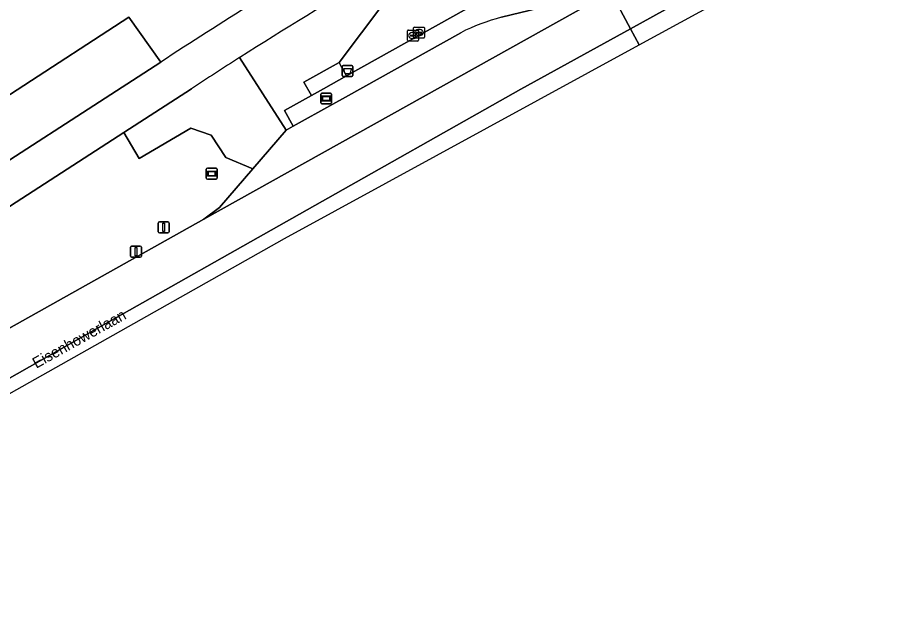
# Model space of a CAD drawing. Extents: x 162417 to 163722, y 384268 to 385417.
# Drawn here: x 163642.7 to 163721.7, y 384656 to 384709.9 of the extents above; entities that cross this region are included whole.
import ezdxf

# ---------------------------------------------------------------- set-up
doc = ezdxf.new("R2010")
doc.units = 0
for name, color, linetype in [('IMGEO_Afvalbak', 7, 'Continuous'), ('IMGEO_Berm_groen', 7, 'Continuous'), ('IMGEO_Fietspad_gesloten', 7, 'Continuous'), ('IMGEO_Informatiebord', 7, 'Continuous'), ('IMGEO_Lichtmast', 7, 'Continuous'), ('IMGEO_Openbare_ruimte_label', 7, 'Continuous'), ('IMGEO_Reclamebord', 7, 'Continuous'), ('IMGEO_Rijbaan_lokaal_open', 7, 'Continuous'), ('IMGEO_Rijbaan_regionaal_gesloten', 7, 'Continuous'), ('IMGEO_Rioolput', 7, 'Continuous'), ('IMGEO_Terreindeel_gesloten', 7, 'Continuous'), ('IMGEO_Terreindeel_halfverhard', 7, 'Continuous'), ('IMGEO_Verkeersbordpaal', 7, 'Continuous'), ('IMGEO_Voetpad_halfverhard', 7, 'Continuous'), ('IMGEO_Voetpad_open', 7, 'Continuous')]:
    doc.layers.add(name, color=color, linetype=linetype)

msp = doc.modelspace()

# ---------------------------------------------------------------- linework, layer by layer
at = {"layer": 'IMGEO_Afvalbak'}
for p, q in [((163672.383, 384704.576), (163672.383, 384705.376)), ((163672.383, 384705.376), (163672.383, 384704.576)), ((163672.483, 384705.476), (163673.273, 384705.476)), ((163673.273, 384705.476), (163672.483, 384705.476)), ((163673.373, 384705.376), (163673.373, 384704.576)), ((163673.373, 384704.576), (163673.373, 384705.376)), ((163673.273, 384704.476), (163672.483, 384704.476)), ((163672.483, 384704.476), (163673.273, 384704.476))]:
    msp.add_line(p, q, dxfattribs=at)
msp.add_lwpolyline([(163672.526, 384705.19), (163673.23, 384705.19), (163673.081, 384704.72), (163672.675, 384704.72), (163672.526, 384705.19)], dxfattribs=at)
for centre, start, end in [((163672.483, 384705.376), 90, 180), ((163672.483, 384705.376), 90, 180), ((163673.273, 384705.376), 0, 90), ((163673.273, 384705.376), 360, 90), ((163672.483, 384704.576), 180, 270), ((163672.483, 384704.576), 180, 270), ((163673.273, 384704.576), 270, 0), ((163673.273, 384704.576), 270, 0)]:
    msp.add_arc(centre, 0.1, start, end, dxfattribs=at)
at = {"layer": 'IMGEO_Berm_groen'}
for points in [[(163692.889, 384718.503), (163690.59, 384722.628), (163688.568, 384721.535), (163688.468, 384721.476), (163688.345, 384721.403), (163680.283, 384716.65), (163672.102, 384705.753), (163672.235, 384705.515), (163672.785, 384704.533), (163691.972, 384715.272)], [(163663.012, 384706.199), (163667.257, 384699.571), (163667.912, 384699.935), (163667.118, 384701.361), (163669.571, 384702.734), (163668.888, 384703.955), (163672.102, 384705.753), (163680.283, 384716.65)], [(163469.772, 384672.33), (163467.865, 384674.003), (163466.183, 384675.435), (163461.935, 384678.823), (163460.408, 384679.673), (163457.666, 384674.338), (163458.848, 384673.73), (163458.908, 384673.806), (163474.172, 384657.022), (163503.834, 384668.371), (163520.825, 384669.345), (163543.475, 384681.474), (163585.432, 384691.917), (163602.43, 384671.194), (163617.872, 384681.245), (163635.32, 384692.539), (163632.434, 384696.611), (163652.863, 384709.886), (163655.792, 384705.79)], [(163476.382, 384588.124), (163492.12, 384597.111), (163500, 384601.57), (163508.776, 384606.535), (163525.426, 384615.965), (163526.577, 384616.616), (163542.052, 384625.367), (163557.44, 384634.061), (163659.74, 384691.409), (163661.179, 384692.489), (163664.218, 384696.03), (163661.732, 384697.059), (163660.417, 384699.089), (163658.56, 384699.737), (163653.811, 384696.957), (163652.418, 384699.337), (163612.308, 384673.403), (163573.184, 384647.901)]]:
    msp.add_lwpolyline(points, dxfattribs=at)
msp.add_lwpolyline([(163655.792, 384705.79), (163652.863, 384709.886), (163632.434, 384696.611), (163635.32, 384692.539)], close=True, dxfattribs=at)
for centre, radius, start, end in [((163902.985, 384327.725), 451.705, 120.64405, 123.17823), ((163626.051, 384738.151), 30.282, 288.15441, 305.28252), ((163855.208, 384405.623), 356.77, 120.27109, 122.59592)]:
    msp.add_arc(centre, radius, start, end, dxfattribs=at)
at = {"layer": 'IMGEO_Fietspad_gesloten'}
for points in [[(163655.792, 384705.79), (163635.32, 384692.539), (163617.872, 384681.245), (163602.43, 384671.194), (163569.274, 384649.613)], [(163573.184, 384647.901), (163612.308, 384673.403), (163652.418, 384699.337), (163658.622, 384703.348)]]:
    msp.add_lwpolyline(points, dxfattribs=at)
for centre, radius, start, end in [((163902.985, 384327.725), 451.705, 120.64405, 123.17823), ((163855.208, 384405.623), 356.77, 120.27109, 122.59592), ((163850.164, 384413.214), 347.658, 122.56958, 123.43227)]:
    msp.add_arc(centre, radius, start, end, dxfattribs=at)
at = {"layer": 'IMGEO_Informatiebord'}
for p, q in [((163670.433, 384702.058), (163670.433, 384702.858)), ((163670.433, 384702.858), (163670.433, 384702.058)), ((163670.533, 384702.958), (163671.323, 384702.958)), ((163671.323, 384702.958), (163670.533, 384702.958)), ((163671.423, 384702.858), (163671.423, 384702.058)), ((163671.423, 384702.058), (163671.423, 384702.858)), ((163671.323, 384701.958), (163670.533, 384701.958)), ((163670.533, 384701.958), (163671.323, 384701.958))]:
    msp.add_line(p, q, dxfattribs=at)
for points in [[(163670.534, 384702.69), (163671.322, 384702.69), (163671.322, 384702.226), (163670.534, 384702.226), (163670.534, 384702.69)], [(163670.599, 384702.625), (163670.599, 384702.291), (163671.257, 384702.291), (163671.257, 384702.625), (163670.599, 384702.625)]]:
    msp.add_lwpolyline(points, dxfattribs=at)
for centre, start, end in [((163670.533, 384702.858), 90, 180), ((163670.533, 384702.858), 90, 180), ((163671.323, 384702.858), 0, 90), ((163671.323, 384702.858), 360, 90), ((163670.533, 384702.058), 180, 270), ((163670.533, 384702.058), 180, 270), ((163671.323, 384702.058), 270, 0), ((163671.323, 384702.058), 270, 0)]:
    msp.add_arc(centre, 0.1, start, end, dxfattribs=at)
at = {"layer": 'IMGEO_Lichtmast'}
for p, q in [((163653.032, 384688.048), (163653.032, 384688.848)), ((163653.032, 384688.848), (163653.032, 384688.048)), ((163653.132, 384688.948), (163653.922, 384688.948)), ((163653.922, 384688.948), (163653.132, 384688.948)), ((163654.022, 384688.848), (163654.022, 384688.048)), ((163654.022, 384688.048), (163654.022, 384688.848)), ((163653.922, 384687.948), (163653.132, 384687.948)), ((163653.132, 384687.948), (163653.922, 384687.948))]:
    msp.add_line(p, q, dxfattribs=at)
msp.add_lwpolyline([(163653.452, 384688.823), (163653.602, 384688.823), (163653.602, 384688.073), (163653.452, 384688.073), (163653.452, 384688.823)], dxfattribs=at)
for centre, start, end in [((163653.132, 384688.848), 90, 180), ((163653.132, 384688.848), 90, 180), ((163653.922, 384688.848), 0, 90), ((163653.922, 384688.848), 360, 90), ((163653.132, 384688.048), 180, 270), ((163653.132, 384688.048), 180, 270), ((163653.922, 384688.048), 270, 0), ((163653.922, 384688.048), 270, 0)]:
    msp.add_arc(centre, 0.1, start, end, dxfattribs=at)
at = {"layer": 'IMGEO_Reclamebord'}
for p, q in [((163659.961, 384695.18), (163659.961, 384695.98)), ((163659.961, 384695.98), (163659.961, 384695.18)), ((163660.061, 384696.08), (163660.851, 384696.08)), ((163660.851, 384696.08), (163660.061, 384696.08)), ((163660.951, 384695.98), (163660.951, 384695.18)), ((163660.951, 384695.18), (163660.951, 384695.98)), ((163660.851, 384695.08), (163660.061, 384695.08)), ((163660.061, 384695.08), (163660.851, 384695.08))]:
    msp.add_line(p, q, dxfattribs=at)
for points in [[(163660.062, 384695.812), (163660.85, 384695.812), (163660.85, 384695.348), (163660.062, 384695.348), (163660.062, 384695.812)], [(163660.127, 384695.747), (163660.127, 384695.413), (163660.785, 384695.413), (163660.785, 384695.747), (163660.127, 384695.747)]]:
    msp.add_lwpolyline(points, dxfattribs=at)
for centre, start, end in [((163660.061, 384695.98), 90, 180), ((163660.061, 384695.98), 90, 180), ((163660.851, 384695.98), 0, 90), ((163660.851, 384695.98), 360, 90), ((163660.061, 384695.18), 180, 270), ((163660.061, 384695.18), 180, 270), ((163660.851, 384695.18), 270, 0), ((163660.851, 384695.18), 270, 0)]:
    msp.add_arc(centre, 0.1, start, end, dxfattribs=at)
at = {"layer": 'IMGEO_Rijbaan_lokaal_open'}
for points in [[(163683.228, 384708.476), (163672.69, 384702.594), (163671.537, 384701.952), (163667.912, 384699.935), (163667.257, 384699.571), (163664.218, 384696.03), (163661.179, 384692.489), (163659.74, 384691.409), (163696.946, 384712.201)], [(163695.757, 384712.017), (163690.358, 384710.71), (163686.959, 384709.888)]]:
    msp.add_lwpolyline(points, dxfattribs=at)
msp.add_arc((163691.532, 384692.168), 18.301, 104.47196, 116.98642, dxfattribs=at)
at = {"layer": 'IMGEO_Rijbaan_regionaal_gesloten'}
for points in [[(163720.897, 384721.078), (163719.207, 384724.346), (163699.749, 384713.787), (163699.243, 384713.496), (163699.075, 384713.399), (163698.53, 384713.086), (163696.946, 384712.201), (163698.754, 384708.845)], [(163699.553, 384707.362), (163721.729, 384719.468), (163720.897, 384721.078), (163698.754, 384708.845)], [(163124.264, 384376.647), (163154.214, 384393.894), (163262.486, 384457.037), (163488.662, 384588.942), (163667.108, 384689.65), (163699.553, 384707.362), (163698.754, 384708.845), (163688.73, 384703.305), (163649.638, 384681.228), (163618.533, 384663.566), (163596.045, 384651.581), (163528.5, 384613.585), (163468.247, 384579.241), (163409.885, 384545.975), (163340.634, 384506.16), (163340.62, 384506.152), (163245.344, 384450.732), (163192.965, 384420.029), (163150.615, 384395.072), (163132.36, 384384.338), (163123.086, 384378.886)]]:
    msp.add_lwpolyline(points, close=True, dxfattribs=at)
for points in [[(163698.754, 384708.845), (163696.946, 384712.201), (163659.74, 384691.409), (163557.44, 384634.061)], [(163125.209, 384384.527), (163121.264, 384382.351), (163122.967, 384379.112), (163123.086, 384378.886), (163132.36, 384384.338), (163150.615, 384395.072), (163192.965, 384420.029), (163245.344, 384450.732), (163340.62, 384506.152), (163340.634, 384506.16), (163409.885, 384545.975), (163468.247, 384579.241), (163528.5, 384613.585), (163596.045, 384651.581), (163618.533, 384663.566), (163649.638, 384681.228), (163688.73, 384703.305), (163698.754, 384708.845)]]:
    msp.add_lwpolyline(points, dxfattribs=at)
at = {"layer": 'IMGEO_Rioolput'}
for p, q in [((163678.363, 384707.792), (163678.363, 384708.644)), ((163678.438, 384708.718), (163679.29, 384708.718)), ((163678.851, 384708.498), (163678.876, 384708.498)), ((163678.913, 384708.06), (163678.913, 384708.912)), ((163678.988, 384708.986), (163679.84, 384708.986)), ((163679.172, 384708.48), (163679.172, 384708.492)), ((163679.61, 384708.443), (163679.212, 384708.443)), ((163679.215, 384708.529), (163679.613, 384708.529)), ((163679.364, 384708.644), (163679.364, 384707.792)), ((163679.401, 384708.766), (163679.426, 384708.766)), ((163679.656, 384708.492), (163679.656, 384708.48)), ((163679.914, 384708.912), (163679.914, 384708.06)), ((163679.29, 384707.718), (163678.438, 384707.718)), ((163678.622, 384708.212), (163678.622, 384708.224)), ((163679.06, 384708.175), (163678.662, 384708.175)), ((163678.665, 384708.261), (163679.063, 384708.261)), ((163678.874, 384707.938), (163678.849, 384707.938)), ((163679.84, 384707.986), (163678.988, 384707.986)), ((163679.106, 384708.224), (163679.106, 384708.212)), ((163679.424, 384708.206), (163679.399, 384708.206))]:
    msp.add_line(p, q, dxfattribs=at)
for points in [[(163678.363, 384707.792), (163678.363, 384708.644)], [(163678.438, 384708.718), (163679.29, 384708.718)], [(163678.913, 384708.06), (163678.913, 384708.912)], [(163678.988, 384708.986), (163679.84, 384708.986)], [(163679.364, 384708.644), (163679.364, 384707.792)], [(163679.914, 384708.912), (163679.914, 384708.06)], [(163679.29, 384707.718), (163678.438, 384707.718)], [(163679.84, 384707.986), (163678.988, 384707.986)]]:
    msp.add_lwpolyline(points, dxfattribs=at)
for centre, radius, start, end in [((163678.44, 384708.642), 0.0765, 91.55205, 178.44795), ((163678.44, 384708.642), 0.0765, 91.55205, 178.44795), ((163678.99, 384708.91), 0.0765, 91.55205, 178.44795), ((163678.99, 384708.91), 0.0765, 91.55205, 178.44795), ((163679.212, 384708.489), 0.0403, 85.87752, 175.75265), ((163679.209, 384708.479), 0.0366, 178.93798, 274.71019), ((163679.288, 384708.642), 0.0765, 1.55205, 88.44795), ((163679.288, 384708.642), 0.0765, 1.55205, 88.44795), ((163679.613, 384708.486), 0.043, 264.86636, 352.45326), ((163679.617, 384708.491), 0.0386, 1.73085, 96.63898), ((163679.838, 384708.91), 0.0765, 1.55205, 88.44795), ((163679.838, 384708.91), 0.0765, 1.55205, 88.44795), ((163678.44, 384707.794), 0.0765, 181.55205, 268.44795), ((163678.44, 384707.794), 0.0765, 181.55205, 268.44795), ((163678.662, 384708.221), 0.0403, 85.87752, 175.75265), ((163678.659, 384708.211), 0.0366, 178.93798, 274.71019), ((163678.99, 384708.062), 0.0765, 181.55205, 268.44795), ((163678.99, 384708.062), 0.0765, 181.55205, 268.44795), ((163679.063, 384708.218), 0.043, 264.86636, 352.45326), ((163679.067, 384708.223), 0.0386, 1.73085, 96.63898), ((163679.288, 384707.794), 0.0765, 271.55205, 358.44795), ((163679.288, 384707.794), 0.0765, 271.55205, 358.44795), ((163679.838, 384708.062), 0.0765, 271.55205, 358.44795), ((163679.838, 384708.062), 0.0765, 271.55205, 358.44795)]:
    msp.add_arc(centre, radius, start, end, dxfattribs=at)
for centre, major_axis, ratio, start_param, end_param in [((163678.85, 384708.218), (-0.387, 0.002), 0.722429, 4.712389, 7.853982), ((163678.875, 384708.218), (-0.39, 0.002), 0.717154, 1.570796, 4.712389), ((163679.4, 384708.486), (-0.387, 0.002), 0.722429, 4.712389, 7.853982), ((163679.425, 384708.486), (-0.39, 0.002), 0.717154, 1.570796, 4.712389)]:
    msp.add_ellipse(centre, major_axis=major_axis, ratio=ratio, start_param=start_param, end_param=end_param, dxfattribs=at)
at = {"layer": 'IMGEO_Terreindeel_gesloten'}
msp.add_lwpolyline([(163672.785, 384704.533), (163672.235, 384705.515), (163672.102, 384705.753), (163668.888, 384703.955), (163669.571, 384702.734), (163670.668, 384703.348)], close=True, dxfattribs=at)
at = {"layer": 'IMGEO_Terreindeel_halfverhard'}
msp.add_lwpolyline([(163658.622, 384703.348), (163652.418, 384699.337), (163653.811, 384696.957), (163658.56, 384699.737), (163660.417, 384699.089), (163661.732, 384697.059), (163664.218, 384696.03), (163667.257, 384699.571), (163663.012, 384706.199)], dxfattribs=at)
msp.add_arc((163850.164, 384413.214), 347.658, 122.56958, 123.43227, dxfattribs=at)
at = {"layer": 'IMGEO_Verkeersbordpaal'}
for p, q in [((163655.567, 384690.264), (163655.567, 384691.064)), ((163655.567, 384691.064), (163655.567, 384690.264)), ((163655.667, 384691.164), (163656.457, 384691.164)), ((163656.457, 384691.164), (163655.667, 384691.164)), ((163656.557, 384691.064), (163656.557, 384690.264)), ((163656.557, 384690.264), (163656.557, 384691.064)), ((163656.457, 384690.164), (163655.667, 384690.164)), ((163655.667, 384690.164), (163656.457, 384690.164))]:
    msp.add_line(p, q, dxfattribs=at)
msp.add_lwpolyline([(163655.987, 384691.039), (163656.137, 384691.039), (163656.137, 384690.289), (163655.987, 384690.289), (163655.987, 384691.039)], dxfattribs=at)
for centre, start, end in [((163655.667, 384691.064), 90, 180), ((163655.667, 384691.064), 90, 180), ((163656.457, 384691.064), 0, 90), ((163656.457, 384691.064), 360, 90), ((163655.667, 384690.264), 180, 270), ((163655.667, 384690.264), 180, 270), ((163656.457, 384690.264), 270, 0), ((163656.457, 384690.264), 270, 0)]:
    msp.add_arc(centre, 0.1, start, end, dxfattribs=at)
at = {"layer": 'IMGEO_Voetpad_halfverhard'}
msp.add_arc((163626.051, 384738.151), 30.282, 288.15441, 305.28252, dxfattribs=at)
at = {"layer": 'IMGEO_Voetpad_open'}
for points in [[(163691.972, 384715.272), (163672.785, 384704.533), (163670.668, 384703.348), (163669.571, 384702.734), (163667.118, 384701.361), (163667.912, 384699.935), (163671.537, 384701.952), (163672.69, 384702.594), (163683.228, 384708.476)], [(163686.959, 384709.888), (163690.358, 384710.71)]]:
    msp.add_lwpolyline(points, dxfattribs=at)
msp.add_arc((163691.532, 384692.168), 18.301, 104.47196, 116.98642, dxfattribs=at)

# ---------------------------------------------------------------- texts
at = {"layer": 'IMGEO_Openbare_ruimte_label'}
msp.add_text('Eisenhowerlaan', height=1, rotation=29.02677, dxfattribs=at).set_placement((163644.409, 384677.729))

doc.saveas('drawing.dxf')
